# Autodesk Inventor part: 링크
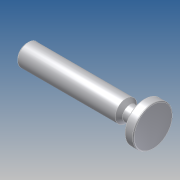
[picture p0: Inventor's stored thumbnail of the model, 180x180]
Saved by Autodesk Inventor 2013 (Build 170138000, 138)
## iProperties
Company: 한국ATC센터
Created: 2009-02
Part Number: 링크
Document SubType Name: Modeling
Designer: KYOUNG IL JANG
Density: 7.86 g/cm^3
Mass: 68.0563 g
Surface Area: 34.7349 cm^2
Volume: 8.65856 cm^3
Material: 강, 연강
Vendor: CBT Solutions
Author: KYOUNG IL JANG
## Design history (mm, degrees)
sketch "스케치1"
  geometry: L1 (-35, 0)-(35, 0); L2 (35, 0)-(35, 11); L3 (35, 11)-(30, 11); L4 (30, 11)-(30, 4); L5 (30, 4)-(22, 4); L6 (22, 4)-(20, 6); L7 (20, 6)-(-35, 6); L8 (-35, 6)-(-35, 0); 1 further point
  constraints: 16 end point, 4 parallel, 2 midpoint, 2 perpendicular, 1 horizontal
  dimensions: "d0" = 70 distance of L1.start L1.end; "d1" = 12 diameter of L7 L1; "d2" = 22 diameter of L3 L1; "d3" = 5 distance of L2.end L3.end; "d4" = 8 diameter of L5 L1; "d5" = 135 deg angle of L6 L5; "d6" = 15 distance from line of L2 L6.end
revolve "회전1" sketch "스케치1" stored, may be unused: angle "d7" = 90 deg
chamfer "모따기1" distance "d8" = 1; stored, may be unused: second distance "d9" = 2, angle "d10" = 45 deg
fillet "모깎기1" dims "d11" = 0.5
node "솔리드1"
